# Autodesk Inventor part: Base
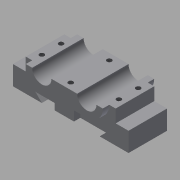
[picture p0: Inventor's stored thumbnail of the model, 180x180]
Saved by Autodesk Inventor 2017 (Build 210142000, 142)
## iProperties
Shininess: 77.0
Length Units: 11269
Angle Units: 11279
Time Units: 11290
Mass Units: 11283
Length Display Precision: 3
Angle Display Precision: 2
Created: 2002-02
Part Number: Base
Document SubType Name: Modeling
Designer: ***
Density: 1 g/cm^3
Material: Generic
Appearance: Default
Density: 0.0
Volumn: 0.0
Area: 0.0
PropertySet Name: Model Information
Control State: 0
Master: False
Checked Out: False
Author: ***
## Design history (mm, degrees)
sketch "Sketch2"
  geometry: L1 (-10.066, -1.263)-(24.934, -1.263); L2 (37.434, 11.237)-(32.434, 11.237); L3 (17.434, 11.237)-(-2.566, 11.237); L4 (-17.566, 11.237)-(-22.566, 11.237); A1 r 12.5 centre (-10.066, 11.237) between (-22.566, 11.237) and (-10.066, -1.263); A2 r 12.5 centre (24.934, 11.237) between (24.934, -1.263) and (37.434, 11.237); A3 r 7.5 centre (24.934, 11.237) between (17.434, 11.237) and (32.434, 11.237); A4 r 7.5 centre (-10.066, 11.237) between (-17.566, 11.237) and (-2.566, 11.237)
  constraints: 8 end point, 8 point on circle, 4 centre point, 3 horizontal, 3 parallel, 2 coincident, 2 equal radius, 2 tangent
  dimensions: "d0" = 12.5 radius of A1; "d1" = 7.5 radius of A4; "d2" = 35 distance of A1.centre A2.centre; "d3" = 12.5 distance between parallel lines of L3 L1
extrude "Extrusion1" new body sketch "Sketch2" stored distance "d4" = 40; taper "d5" = 0 deg
sketch "Sketch4"
  geometry: L1 (-27.566, 1.237)-(-37.566, 1.237); L2 (-37.566, 1.237)-(-37.566, -13.763); L3 (-37.566, -13.763)-(-15.066, -13.763); L4 (-15.066, -13.763)-(-20.066, -8.763); L5 (-20.066, -8.763)-(34.934, -8.763); L6 (34.934, -8.763)-(29.934, -13.763); L7 (29.934, -13.763)-(52.434, -13.763); L8 (52.434, -13.763)-(52.434, 1.237); L9 (52.434, 1.237)-(42.434, 1.237); L10 (24.934, -1.263)-(-10.066, -1.263); L11 (-17.566, 11.237)-(-22.566, 11.237) reference; L12 (37.434, 11.237)-(32.434, 11.237) reference; L13 (-22.566, 11.237)-(-27.566, 11.237); L14 (-27.566, 11.237)-(-27.566, 1.237); L15 (37.434, 11.237)-(42.434, 11.237); L16 (42.434, 11.237)-(42.434, 1.237); A1 r 12.5 centre (24.934, 11.237) between (24.934, -1.263) and (37.434, 11.237); A2 r 12.5 centre (-10.066, 11.237) between (-22.566, 11.237) and (-10.066, -1.263); A3 r 12.5 centre (24.934, 11.237) between (24.934, -1.263) and (37.434, 11.237) reference; A4 r 12.5 centre (-10.066, 11.237) between (-22.566, 11.237) and (-10.066, -1.263) reference
  constraints: 28 end point, 6 perpendicular, 5 equal length, 4 concentric, 4 parallel, 4 point on circle, 2 centre point, 2 collinear, 1 tangent
  dimensions: "d12" = 15 distance of L1.end L2.end; "d13" = 25 distance from line of L3 L11.end; "d14" = 90 distance between parallel lines of L2 L8; "d15" = 5 distance between parallel lines of L5 L7; "d16" = 22.5 distance of L2.end L3.end; "d24" = 5 distance of L12.start L15.end; "d25" = 15 distance from line of L8 L12.start
extrude "Extrusion3" join sketch "Sketch4" stored distance "d17" = 30; taper "d18" = 0 deg
sketch "Sketch5"
  geometry: L1 (-14.934, -1.263)-(0.066, -1.263); L2 (0.066, -1.263)-(0.066, -8.763); L3 (0.066, -8.763)-(-14.934, -8.763); L4 (-14.934, -8.763)-(-14.934, -1.263); L5 (10.066, -1.263)-(-24.934, -1.263) reference; 1 further point
  constraints: 8 end point, 2 parallel, 1 collinear, 1 horizontal, 1 perpendicular
  dimensions: "d19" = 7.5 distance of L1.end L2.end; "d20" = 15 distance of L2.end L3.end; "d21" = 15 distance from line of point (-29.934, -13.763) L4
extrude "Extrusion4" join sketch "Sketch5" distance "d22" = 40; taper "d23" = 0 deg
sketch "Sketch6"
  geometry: L1 (-5, -35)-(0, -35) reference; L2 (-5, -35)-(-5, -5) reference; 1 further point
  dimensions: "d26" = 7.5 distance from line of L1 point (0, -27.5); "d27" = 5 distance from line of L2 point (0, -27.5)
hole "Hole1" sketch "Sketch6" at (0, -27.5) diameter "d28" = 3.688; stored, may be unused: countersink angle "d32" = 82 deg, drill point angle "d34" = 0 deg; dims "d29" = 9, "d30" = 4, "d31" = 2, "d33" = 15
pattern_linear "Rectangular Pattern1" dims "d37" = 60, "d40" = 15
sketch "Sketch7"
  geometry: L1 (-20, -40)-(-20, -35) reference; L2 (0, -40)-(20, -40) reference; 1 further point
  dimensions: "d41" = 30 distance from line of L1 point (10, -35); "d42" = 5 distance from line of L2 point (10, -35)
hole "Hole2" sketch "Sketch7" at (10, -35) diameter "d43" = 3.688; stored, may be unused: countersink angle "d47" = 82 deg, drill point angle "d49" = 0 deg; dims "d44" = 9, "d45" = 4, "d46" = 2, "d48" = 15
pattern_linear "Rectangular Pattern2" dims "d52" = 30
body "Solid1"
